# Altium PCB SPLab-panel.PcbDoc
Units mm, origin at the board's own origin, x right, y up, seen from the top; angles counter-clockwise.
Board outline 58.42 x 28.92 mm, 2 copper layers (TopLayer, BottomLayer), stack 1.671 mm thick; 5 components, 5 nets, 13 pads, 0 vias.
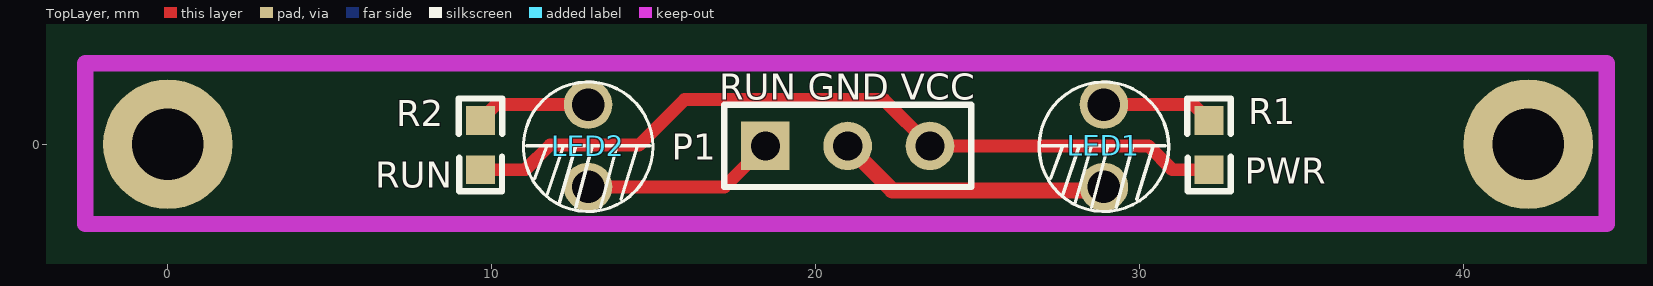
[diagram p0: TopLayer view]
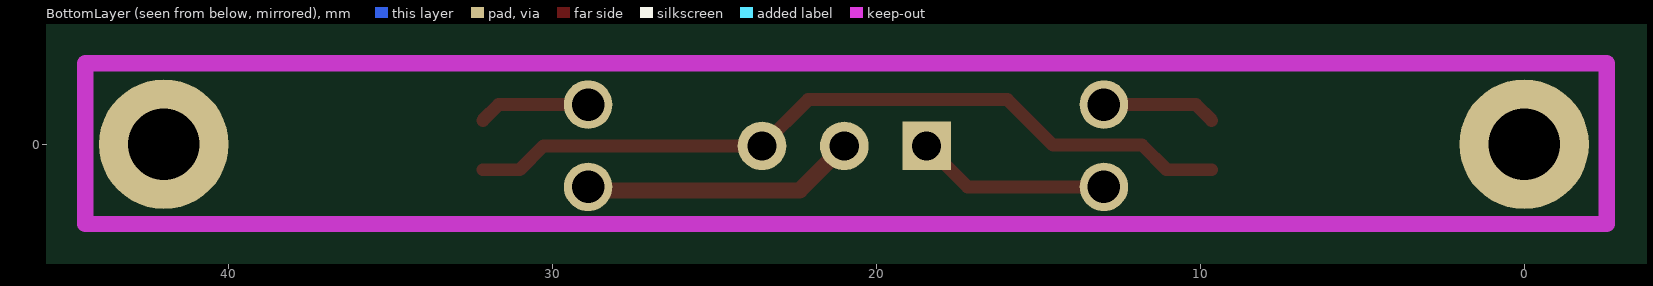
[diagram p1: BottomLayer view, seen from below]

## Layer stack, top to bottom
TopLayer: signal copper 0.0356
Dielectric: core 1.6, FR-4, Dk 4.8
BottomLayer: signal copper 0.0356

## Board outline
-7.575,-13.525 50.85,-13.525 50.85,15.4 -7.575,15.4

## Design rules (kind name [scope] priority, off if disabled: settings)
Clearance Clearance_poly [InPolygon] p1: gap=0.3
Clearance [All] p2: gap=0.15
ComponentClearance [All] p1: gap=0.15 collisioncheckmode=3 verticalgap=0.254 showdistances=FALSE
FabricationTestPointUsage TestPointUsage [All] p1: valid=0 allowmultiple=FALSE
FabricationTestpoint Testpoint [All] p1: side=3 testpointundercomponent=TRUE minsize=1.016 maxsize=2.54 preferedsize=1.524 minholesize=0.508 maxholesize=1.016 preferedholesize=0.813 testpointgrid=0.025 allowsidetop=TRUE allowsidebottom=TRUE usegrid=TRUE gridtolerance=0
HoleSize [All] p1: absolutevalues=TRUE maxlimit=5.08 minlimit=0.025 maxpercent=80.000 minpercent=20.000
MinimumSolderMaskSliver [All] p1: minsoldermaskwidth=0.15
PlaneClearance [All] p1: clearance=0.5
PlaneConnect [All] p1: planeconnectstyle=Relief reliefexpansion=0.5 reliefentries=4 reliefconductorwidth=0.3 reliefairgap=0.3
PolygonConnect PolygonConnect_via [IsVia] p1: connectstyle=Direct reliefconductorwidth=0.254 reliefentries=4 polygonreliefangle="90 Angle"
PolygonConnect [All] p2: connectstyle=Relief reliefconductorwidth=0.3 reliefentries=4 polygonreliefangle="90 Angle"
RoutingVias [All] p1: holewidth=0.305 width=0.61 viastyle="Through Hole" minholewidth=0.254 minwidth=0.508 maxholewidth=2 maxwidth=5
SilkToSilkClearance [All] p1: silktosilkclearance=0
SilkscreenOverComponentPads [All] p1: minsilkscreentomaskgap=0
SolderMaskExpansion [All] p1: expansion=0.102
Width [All] p1: maxlimit=5.08 minlimit=0.1 preferedwidth=0.254
19 further rules are at their usual default settings.

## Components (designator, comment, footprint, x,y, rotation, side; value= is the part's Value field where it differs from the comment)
LED1 "PWR" LED 28.9,1.225 r270 top
LED2 "RUN" LED 12.975,1.225 r270 top
P1 "Header 3" HDR1X3 18.45,-0.05 r0 top
R1 "1K" SM0603 32.2,-0.025 r270 top
R2 "1K" SM0603 9.7,-0.025 r270 top

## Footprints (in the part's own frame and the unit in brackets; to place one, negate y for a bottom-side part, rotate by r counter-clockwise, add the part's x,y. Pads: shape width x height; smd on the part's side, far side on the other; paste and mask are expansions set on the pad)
HDR1X3 [mm] "Connector; Header; 3 Position"
  rect 1.5x1.5 hole 0.9: 1(0,0)
  round 1.5 hole 0.9: 2(2.54,0) 3(5.08,0)
  silkscreen extent -1.27,-1.27 6.35,1.27
LED [mm]
  round 1.5 hole 1: 1(0,0) 2(2.54,0)
  silkscreen extent -0.7,-2 3.3,2
SM0603 [mil]
  rect 35x35 smd: 1(-30,-2) 2(30,-2)
  silkscreen extent -57,-28 56,24

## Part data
LED1 LED2: library part LED0, "Typical INFRARED GaAs LED"
P1: "Header, 3-Pin"
R1 R2: library part R, "电?"

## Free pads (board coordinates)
  round 4 hole 2.2: 1(0,0) 1(42,0)

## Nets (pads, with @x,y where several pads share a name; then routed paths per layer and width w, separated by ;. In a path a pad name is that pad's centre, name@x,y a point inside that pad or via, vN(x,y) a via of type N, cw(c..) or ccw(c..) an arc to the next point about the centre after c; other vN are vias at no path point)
GND: LED1.2 P1.2 | length 8.5
  TopLayer w0.5: P1.2 22.365,-1.425 28.79,-1.425 LED1.2
LED_S2: LED2.2 P1.1 | length 6
  TopLayer w0.4: LED2.2 17.185,-1.315 P1.1
NetLED1_1: LED1.1 R1.1 | length 3.5
  TopLayer w0.4: LED1.1 31.661,1.225 R1.1
NetLED2_1: LED2.1 R2.1 | length 3.5
  TopLayer w0.4: R2.1 10.137,1.225 LED2.1
VCC3.3: P1.3 R1.2 R2.2 | length 24.3
  TopLayer w0.4: R2.2 11.038,-0.787 11.8,-0.025 14.55,-0.025 15.95,1.375 22.105,1.375 P1.3 30.275,-0.05 31.012,-0.787 R1.2

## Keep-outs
KeepOutLayer:
  lines w0.5: -2.55,-2.466 -2.55,2.5 44.425,2.5 44.425,-2.466 -2.55,-2.466

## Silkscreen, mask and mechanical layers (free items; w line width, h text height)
TopOverlay:
  text "RUN GND VCC" at 17.025,1.375 h0.8
Mechanical1:
  lines w0.3: -3.85,-0.025 53.275,-0.025

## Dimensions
-3.219,0 to -3.65,-2.55 on Mechanical1
0,-5.3 to 12.975,-1.375 on Mechanical1
13,-5.3 to 20.95,-1.175 on Mechanical1
20.95,-5.225 to 28.9,-1.1 on Mechanical1
28.925,-5.075 to 41.9,-1.15 on Mechanical1
-3.194,2.55 to -3.625,0 on Mechanical1
-2.55,-1.469 to 0,-1.9 on Mechanical1
41.875,-1.694 to 44.425,-2.125 on Mechanical1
